// Mitsubishi GX Works2 project: season-Q   PLC: Q06H

PROGRAM MAIN
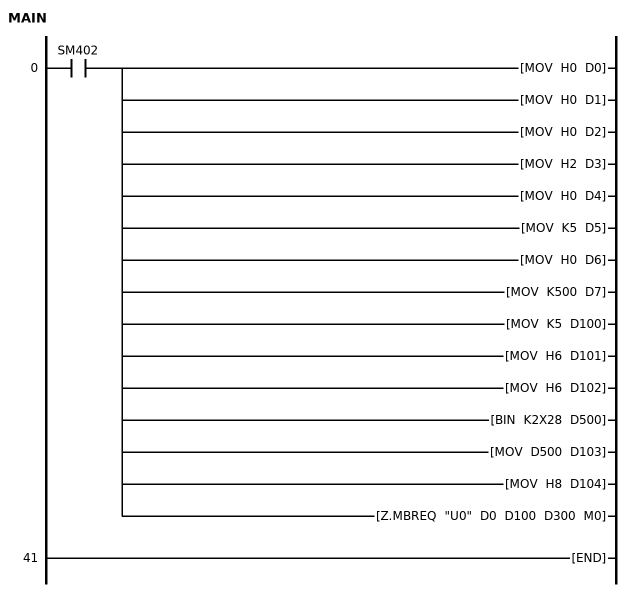
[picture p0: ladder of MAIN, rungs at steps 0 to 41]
0     LD      SM402
      MOV     H0 D0
      MOV     H0 D1
      MOV     H0 D2
      MOV     H2 D3
      MOV     H0 D4
      MOV     K5 D5
      MOV     H0 D6
      MOV     K500 D7
      MOV     K5 D100
      MOV     H6 D101
      MOV     H6 D102
      BIN     K2X28 D500
      MOV     D500 D103
      MOV     H8 D104
      Z.MBREQ "U0" D0 D100 D300 M0
41    END
END_PROGRAM
